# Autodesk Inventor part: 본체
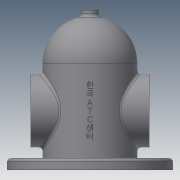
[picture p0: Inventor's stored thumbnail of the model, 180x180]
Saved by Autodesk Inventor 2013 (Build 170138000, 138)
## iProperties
Created: 2019-11
Part Number: 본체
Material: Generic
Document SubType Name: Modeling
Designer: 19
Density: 1 g/cm^3
Author: 19
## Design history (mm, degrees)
sketch "스케치1"
  geometry: L1 (0, -50)-(0, 80); L2 (0, -50)-(40, -50); L3 (40, -50)-(40, 40); A1 r 40 centre (0, 40) between (40, 40) and (0, 80); 2 further points
  constraints: 6 end point, 2 perpendicular, 2 point on circle, 1 centre point, 1 midpoint, 1 vertical, 1 vertical alignment
  dimensions: "d0" = 130 distance of L1.start L1.end; "d2" = 50 distance of point (0, 0) L1.start; "d3" = 90 distance of L2.end L3.end; "d4" = 40 radius of A1; "d5" = 40 distance between parallel lines of L1 L3
revolve "회전1" sketch "스케치1" stored, may be unused: angle "d6" = 90 deg
feature "쉘1" dims "d7" = 10
sketch "스케치2"
  geometry: C1 r 40 at (0, 0) reference; C2 r 70 at (0, 0)
  constraints: 1 centre point, 1 coincident
  dimensions: "d8" = 140 diameter of C2
extrude "돌출1" join sketch "스케치2" distance "d9" = 10; taper "d10" = 0 deg
sketch "스케치3"
  geometry: L1 (0, 0)-(0, 55); L2 (0, 0)-(0, -55); C1 r 70 at (0, 0) reference; 2 further points
  constraints: 4 end point, 2 coincident, 1 collinear, 1 vertical
  dimensions: "d12" = 55 distance of L1.start L1.end; "d13" = 55 distance of L1.start L2.end
hole "구멍1" sketch "스케치3" at (0, 55), (0, -55) diameter "d14" = 9; stored, may be unused: countersink angle "d18" = 90 deg, drill point angle "d20" = 118 deg; dims "d15" = 6, "d16" = 4, "d17" = 2, "d19" = 8
node "작업 평면1"
sketch "스케치4"
  geometry: C1 r 31 at (0, 0); 1 further point
  constraints: 1 centre point, 1 coincident
  dimensions: "d22" = 62 diameter of C1
extrude "돌출2" join sketch "스케치4" stored distance "d23" = 10; taper "d24" = 0 deg
sketch "스케치5"
  geometry: C1 r 31 at (0, 0) reference; C2 r 20 at (0, 0)
  constraints: 1 centre point, 1 coincident
  dimensions: "d25" = 40 diameter of C2
extrude "돌출3" cut sketch "스케치5" distance "d26" = 15; taper "d27" = 0 deg
sketch "스케치6"
  geometry: C1 r 31 at (0, 0) reference; C2 r 20 at (0, 0)
  constraints: 1 centre point, 1 coincident
  dimensions: "d28" = 40 diameter of C2
extrude "돌출4" cut sketch "스케치6" distance "d29" = 15; taper "d30" = 0 deg
sketch "스케치7"
  geometry: C1 r 20 at (0, 0) reference; C2 r 16.5 at (0, 0)
  constraints: 1 centre point, 1 coincident
  dimensions: "d31" = 33 diameter of C2
extrude "돌출5" cut sketch "스케치7" stored distance "d32" = 15; taper "d33" = 0 deg
node "작업 평면2"
sketch "스케치8"
  geometry: C1 r 7.5 at (0, 0); 1 further point
  constraints: 1 centre point, 1 coincident
  dimensions: "d35" = 15 diameter of C1
extrude "돌출6" join sketch "스케치8" stored distance "d36" = 15; taper "d37" = 0 deg
sketch "스케치9"
  geometry: C1 r 7.5 at (0, 0) reference; 1 further point
  constraints: 1 coincident
hole "구멍2" sketch "스케치9" at (0, 0) diameter "d38" = 5.188; stored, may be unused: countersink angle "d42" = 90 deg, drill point angle "d44" = 118 deg; dims "d39" = 6, "d40" = 4, "d41" = 2, "d43" = 8
sketch "스케치10"
  geometry: L1 (0, 0)-(0, 26); C1 r 31 at (0, 0) reference; 1 further point
  constraints: 2 end point, 1 coincident, 1 vertical
  dimensions: "d45" = 26 distance of L1.start L1.end
hole "구멍3" sketch "스케치10" at (0, 26) diameter "d46" = 3.242; stored, may be unused: countersink angle "d50" = 90 deg, drill point angle "d52" = 118 deg; dims "d47" = 8, "d48" = 4, "d49" = 2, "d51" = 10
fillet "모깎기1" dims "d56" = 3
fillet "모깎기2" dims "d57" = 3
fillet "모깎기3" dims "d58" = 3
fillet "모깎기4" dims "d59" = 0.3
chamfer "모따기1" distance "d60" = 1; stored, may be unused: second distance "d61" = 2, angle "d62" = 45 deg
node "작업 평면3"
sketch "스케치11"
  geometry: L1 (70, -50)-(-70, -50) reference; 2 further points
  constraints: 1 coincident, 1 other
  dimensions: "d64" = 50 distance from line of L1 point (0, 0)
feature "엠보싱1" sketch "스케치11" dims "d12" = 55, "d13" = 55, "d65" = 0.5, "d66" = 0
node "솔리드1"
mirror "대칭1"
pattern_circular "원형 패턴1" dims angle "d54" = 360 deg
mirror "대칭2"
other parameters: "d34" = 85
